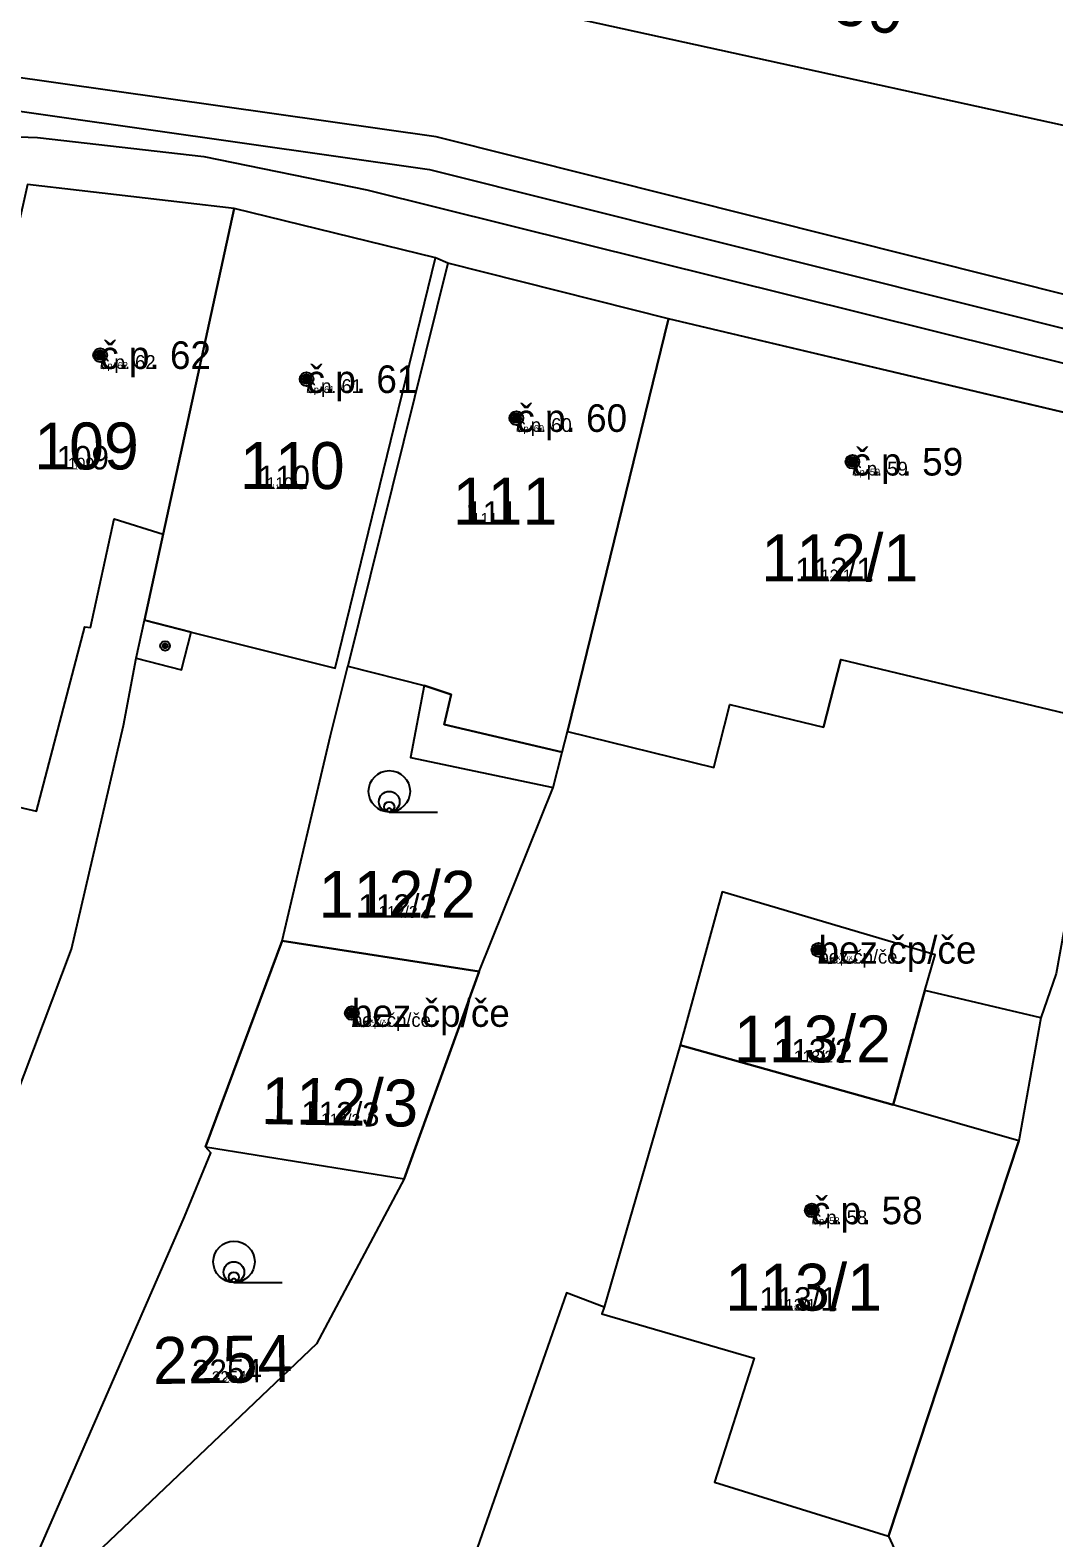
# Model space of a CAD drawing. Extents: x -744652 to -739090, y -980828 to -975855.
# Drawn here: x -742656.4 to -742619.3, y -978675.6 to -978620.9 of the extents above; entities that cross this region are included whole.
import ezdxf

# ---------------------------------------------------------------- set-up
doc = ezdxf.new("R2010")
doc.units = 0
for name, color, linetype in [('KAT_02_hranice parcel', 7, 'Continuous'), ('KAT_03_1000_st čísla parcelní', 7, 'Continuous'), ('KAT_03_1000_čísla parcelní', 7, 'Continuous'), ('KAT_03_1000_čísla popisná', 7, 'Continuous'), ('KAT_03_100_st čísla parcelní', 7, 'Continuous'), ('KAT_03_100_čísla parcelní', 7, 'Continuous'), ('KAT_03_100_čísla popisná', 7, 'Continuous'), ('KAT_03_250_st čísla parcelní', 7, 'Continuous'), ('KAT_03_250_čísla parcelní', 7, 'Continuous'), ('KAT_03_250_čísla popisná', 7, 'Continuous'), ('KAT_03_500_st čísla parcelní', 7, 'Continuous'), ('KAT_03_500_čísla parcelní', 7, 'Continuous'), ('KAT_03_500_čísla popisná', 7, 'Continuous'), ('KAT_04_vnitřní kresba', 7, 'Continuous'), ('KAT_05_1000_značky kultur', 7, 'Continuous'), ('KAT_05_100_značky kultur', 7, 'Continuous'), ('KAT_05_250_značky kultur', 7, 'Continuous'), ('KAT_05_500_značky kultur', 7, 'Continuous'), ('KAT_07_1000_značky budov', 7, 'Continuous'), ('KAT_07_100_značky budov', 7, 'Continuous'), ('KAT_07_500_značky budov', 7, 'Continuous'), ('KAT_10_věcná břemena', 7, 'Continuous'), ('KAT_14_plocha_budovy', 7, 'Continuous')]:
    doc.layers.add(name, color=color, linetype=linetype)

msp = doc.modelspace()

# ---------------------------------------------------------------- linework, layer by layer
at = {"layer": 'KAT_02_hranice parcel'}
for p, q in [((-742648.99, -978627.41), (-742656.48, -978626.54)), ((-742641.69, -978629.19), (-742648.99, -978627.41)), ((-742641.24, -978629.39), (-742644.87, -978643.99)), ((-742641.24, -978629.39), (-742641.69, -978629.19)), ((-742633.24, -978631.41), (-742641.24, -978629.39)), ((-742616.02, -978635.48), (-742633.24, -978631.41)), ((-742640.11, -978655.05), (-742637.43, -978648.38)), ((-742650.02, -978661.4), (-742647.25, -978653.94)), ((-742647.25, -978653.94), (-742640.11, -978655.05)), ((-742640.11, -978655.05), (-742642.83, -978662.56)), ((-742619.75, -978656.72), (-742623.95, -978655.73)), ((-742650.02, -978661.4), (-742642.83, -978662.56))]:
    msp.add_line(p, q, dxfattribs=at)
for points in [[(-742522.65, -978636.07), (-742549.97, -978633.28), (-742570.9, -978630.86), (-742578.86, -978629.74), (-742582.72, -978630.81), (-742604.63, -978627.47), (-742606.59, -978627.11), (-742643.73, -978618.95), (-742648.55, -978617.06), (-742656.38, -978615.82), (-742687.27, -978612.16), (-742690.29, -978611.84), (-742693.32, -978611.73), (-742696.29, -978611.66), (-742699.31, -978611.74), (-742704.32, -978612.08), (-742722.21, -978614.75), (-742725.22, -978615.06), (-742728.22, -978615.18), (-742731.2, -978615.09), (-742734.19, -978614.83)], [(-742703.15, -978625.25), (-742703.26, -978623.39), (-742676.2, -978624.12), (-742656.11, -978624.83), (-742650.09, -978625.52), (-742644.18, -978626.73), (-742615.87, -978633.77)], [(-742652.54, -978643.69), (-742652.24, -978642.32), (-742651.56, -978639.2), (-742648.99, -978627.41)], [(-742652.54, -978643.69), (-742650.89, -978644.12), (-742650.54, -978642.75), (-742645.32, -978644.06), (-742641.69, -978629.19)], [(-742637.43, -978648.38), (-742637.1, -978647.1), (-742636.9, -978646.35), (-742633.24, -978631.41)], [(-742616.02, -978635.48), (-742618.77, -978652.77), (-742619.2, -978655.12), (-742619.75, -978656.72)], [(-742658.67, -978664.27), (-742654.88, -978654.24), (-742653, -978646.13), (-742652.54, -978643.69)], [(-742647.25, -978653.94), (-742645.49, -978646.5), (-742644.87, -978643.99)], [(-742644.87, -978643.99), (-742642.1, -978644.68), (-742642.59, -978647.29), (-742637.43, -978648.38)], [(-742623.95, -978655.73), (-742623.58, -978654.44), (-742631.3, -978652.16), (-742632.82, -978657.71)], [(-742623.95, -978655.73), (-742625.1, -978659.88), (-742632.82, -978657.71)], [(-742619.75, -978656.72), (-742620.55, -978661.18), (-742625.27, -978675.5), (-742624.7, -978676.73), (-742624.09, -978685.66)], [(-742632.82, -978657.71), (-742635.58, -978667.21), (-742636.94, -978666.69), (-742642.55, -978682.7), (-742646.97, -978692.83)], [(-742656.28, -978676.53), (-742650.78, -978663.93), (-742649.83, -978661.61), (-742650.02, -978661.4)], [(-742642.83, -978662.56), (-742646, -978668.53), (-742655.01, -978677.1)]]:
    msp.add_lwpolyline(points, dxfattribs=at)
at = {"layer": 'KAT_03_1000_čísla popisná'}
for centre in [(-742653.84, -978632.72), (-742653.84, -978632.72), (-742646.36, -978633.59), (-742646.36, -978633.59), (-742638.76, -978635), (-742638.76, -978635), (-742626.58, -978636.58), (-742626.58, -978636.58), (-742627.81, -978654.26), (-742627.81, -978654.26), (-742644.72, -978656.55), (-742644.72, -978656.55), (-742628.05, -978663.7), (-742628.05, -978663.7)]:
    msp.add_circle(centre, 0.25, dxfattribs=at)
at = {"layer": 'KAT_03_100_čísla popisná'}
for centre in [(-742653.84, -978632.72), (-742653.84, -978632.72), (-742646.36, -978633.59), (-742646.36, -978633.59), (-742638.76, -978635), (-742638.76, -978635), (-742626.58, -978636.58), (-742626.58, -978636.58), (-742627.81, -978654.26), (-742627.81, -978654.26), (-742644.72, -978656.55), (-742644.72, -978656.55), (-742628.05, -978663.7), (-742628.05, -978663.7)]:
    msp.add_circle(centre, 0.025, dxfattribs=at)
at = {"layer": 'KAT_03_250_čísla popisná'}
for centre in [(-742653.84, -978632.72), (-742653.84, -978632.72), (-742646.36, -978633.59), (-742646.36, -978633.59), (-742638.76, -978635), (-742638.76, -978635), (-742626.58, -978636.58), (-742626.58, -978636.58), (-742627.81, -978654.26), (-742627.81, -978654.26), (-742644.72, -978656.55), (-742644.72, -978656.55), (-742628.05, -978663.7), (-742628.05, -978663.7)]:
    msp.add_circle(centre, 0.0625, dxfattribs=at)
at = {"layer": 'KAT_03_500_čísla popisná'}
for centre in [(-742653.84, -978632.72), (-742653.84, -978632.72), (-742646.36, -978633.59), (-742646.36, -978633.59), (-742638.76, -978635), (-742638.76, -978635), (-742626.58, -978636.58), (-742626.58, -978636.58), (-742627.81, -978654.26), (-742627.81, -978654.26), (-742644.72, -978656.55), (-742644.72, -978656.55), (-742628.05, -978663.7), (-742628.05, -978663.7)]:
    msp.add_circle(centre, 0.125, dxfattribs=at)
at = {"layer": 'KAT_04_vnitřní kresba'}
for p, q in [((-742654.19, -978642.59), (-742653.34, -978638.65)), ((-742653.34, -978638.65), (-742651.56, -978639.2)), ((-742656.15, -978649.24), (-742654.4, -978642.56)), ((-742654.4, -978642.56), (-742654.19, -978642.59)), ((-742650.54, -978642.75), (-742652.24, -978642.32)), ((-742627, -978643.74), (-742627.63, -978646.19)), ((-742627, -978643.74), (-742618.58, -978645.76)), ((-742641.12, -978645.01), (-742642.1, -978644.68)), ((-742641.38, -978646.1), (-742641.12, -978645.01)), ((-742631.6, -978647.66), (-742631.02, -978645.37)), ((-742631.02, -978645.37), (-742627.63, -978646.19)), ((-742637.1, -978647.1), (-742641.38, -978646.1)), ((-742636.9, -978646.35), (-742631.6, -978647.66)), ((-742661.63, -978647.97), (-742656.15, -978649.24)), ((-742620.55, -978661.18), (-742625.1, -978659.88)), ((-742635.58, -978667.21), (-742635.66, -978667.44)), ((-742635.66, -978667.44), (-742630.14, -978669.05)), ((-742630.14, -978669.05), (-742631.58, -978673.54)), ((-742631.58, -978673.54), (-742625.27, -978675.5))]:
    msp.add_line(p, q, dxfattribs=at)
at = {"layer": 'KAT_05_1000_značky kultur'}
for p, q in [((-742643.363, -978649.27), (-742641.613, -978649.27)), ((-742648.993, -978666.31), (-742647.243, -978666.31))]:
    msp.add_line(p, q, dxfattribs=at)
for centre in [(-742643.363, -978648.52), (-742648.993, -978665.56)]:
    msp.add_circle(centre, 0.75, dxfattribs=at)
at = {"layer": 'KAT_05_100_značky kultur'}
for p, q in [((-742643.369, -978649.27), (-742643.194, -978649.27)), ((-742648.999, -978666.31), (-742648.824, -978666.31))]:
    msp.add_line(p, q, dxfattribs=at)
for centre in [(-742643.369, -978649.195), (-742648.999, -978666.235)]:
    msp.add_circle(centre, 0.075, dxfattribs=at)
at = {"layer": 'KAT_05_250_značky kultur'}
for p, q in [((-742643.368, -978649.27), (-742642.931, -978649.27)), ((-742648.998, -978666.31), (-742648.561, -978666.31))]:
    msp.add_line(p, q, dxfattribs=at)
for centre in [(-742643.368, -978649.082), (-742648.998, -978666.122)]:
    msp.add_circle(centre, 0.187, dxfattribs=at)
at = {"layer": 'KAT_05_500_značky kultur'}
for p, q in [((-742643.367, -978649.27), (-742642.492, -978649.27)), ((-742648.997, -978666.31), (-742648.122, -978666.31))]:
    msp.add_line(p, q, dxfattribs=at)
for centre in [(-742643.366, -978648.895), (-742648.996, -978665.935)]:
    msp.add_circle(centre, 0.375, dxfattribs=at)
at = {"layer": 'KAT_07_1000_značky budov'}
for centre in [(-742653.847, -978632.719), (-742646.367, -978633.589), (-742638.767, -978634.999), (-742626.587, -978636.579), (-742651.487, -978643.249), (-742627.817, -978654.259), (-742644.727, -978656.549), (-742628.057, -978663.699)]:
    msp.add_circle(centre, 0.175, dxfattribs=at)
at = {"layer": 'KAT_07_100_značky budov'}
for centre in [(-742653.841, -978632.72), (-742646.361, -978633.59), (-742638.761, -978635), (-742626.581, -978636.58), (-742651.481, -978643.25), (-742627.811, -978654.26), (-742644.721, -978656.55), (-742628.051, -978663.7)]:
    msp.add_circle(centre, 0.0175, dxfattribs=at)
at = {"layer": 'KAT_07_500_značky budov'}
for centre, radius in [((-742653.843, -978632.72), 0.0875), ((-742653.842, -978632.72), 0.0438), ((-742646.363, -978633.59), 0.0875), ((-742646.362, -978633.59), 0.0438), ((-742638.763, -978635), 0.0875), ((-742638.762, -978635), 0.0438), ((-742626.583, -978636.58), 0.0875), ((-742626.582, -978636.58), 0.0438), ((-742651.483, -978643.25), 0.0875), ((-742651.482, -978643.25), 0.0438), ((-742627.813, -978654.26), 0.0875), ((-742627.812, -978654.26), 0.0438), ((-742644.723, -978656.55), 0.0875), ((-742644.722, -978656.55), 0.0438), ((-742628.053, -978663.7), 0.0875), ((-742628.052, -978663.7), 0.0438)]:
    msp.add_circle(centre, radius, dxfattribs=at)
at = {"layer": 'KAT_10_věcná břemena'}
msp.add_lwpolyline([(-742612.55, -978632.12), (-742641.67, -978624.81), (-742669.08, -978620.92), (-742706.88, -978620.85), (-742736.16, -978619.17), (-742737.02, -978621.05), (-742706.92, -978622.05), (-742669.16, -978622.12), (-742641.91, -978625.99), (-742612.75, -978633.3)], dxfattribs=at)
at = {"layer": 'KAT_14_plocha_budovy'}
for points in [[(-742660.03, -978642.4), (-742661.63, -978647.97), (-742656.15, -978649.24), (-742654.4, -978642.56), (-742654.19, -978642.59), (-742653.34, -978638.65), (-742651.56, -978639.2), (-742648.99, -978627.41), (-742656.48, -978626.54)], [(-742652.24, -978642.32), (-742650.54, -978642.75), (-742645.32, -978644.06), (-742641.69, -978629.19), (-742648.99, -978627.41), (-742651.56, -978639.2)], [(-742633.24, -978631.41), (-742641.24, -978629.39), (-742644.87, -978643.99), (-742642.1, -978644.68), (-742641.12, -978645.01), (-742641.38, -978646.1), (-742637.1, -978647.1), (-742636.9, -978646.35)], [(-742633.24, -978631.41), (-742636.9, -978646.35), (-742631.6, -978647.66), (-742631.02, -978645.37), (-742627.63, -978646.19), (-742627, -978643.74), (-742618.58, -978645.76), (-742616.02, -978635.48)], [(-742632.82, -978657.71), (-742625.1, -978659.88), (-742623.95, -978655.73), (-742623.58, -978654.44), (-742631.3, -978652.16)], [(-742647.25, -978653.94), (-742650.02, -978661.4), (-742642.83, -978662.56), (-742640.11, -978655.05)], [(-742635.58, -978667.21), (-742635.66, -978667.44), (-742630.14, -978669.05), (-742631.58, -978673.54), (-742625.27, -978675.5), (-742620.55, -978661.18), (-742625.1, -978659.88), (-742632.82, -978657.71)]]:
    msp.add_lwpolyline(points, close=True, dxfattribs=at)

# ---------------------------------------------------------------- texts
at = {"layer": 'KAT_03_1000_st čísla parcelní'}
for s, p in [('109', (-742656.234, -978636.86)), ('110', (-742648.774, -978637.57)), ('111', (-742641.064, -978638.86)), ('112/1', (-742629.883, -978640.91)), ('113/2', (-742630.873, -978658.34)), ('113/1', (-742631.193, -978667.33))]:
    msp.add_text(s, height=1.7, dxfattribs=at).set_placement(p)
msp.add_text('112/3', height=1.7, rotation=359, dxfattribs=at).set_placement((-742648.017, -978660.571))
at = {"layer": 'KAT_03_1000_čísla parcelní'}
for s, rotation, p in [('2054/50', 349, (-742632.949, -978619.582)), ('2254', 1, (-742651.921, -978669.993))]:
    msp.add_text(s, height=1.7, rotation=rotation, dxfattribs=at).set_placement(p)
msp.add_text('112/2', height=1.7, dxfattribs=at).set_placement((-742645.923, -978653.1))
at = {"layer": 'KAT_03_1000_čísla popisná'}
for s, height, p in [('č.p. 62', 1, (-742653.84, -978633.22)), ('č.p. 61', 1, (-742646.36, -978634.09)), ('č.p. 60', 1, (-742638.76, -978635.5)), ('č.p. 59', 1, (-742626.58, -978637.08)), ('109', 0.017, (-742654.617, -978636.86)), ('110', 0.017, (-742647.502, -978637.57)), ('111', 0.017, (-742640.163, -978638.86)), ('112/1', 0.017, (-742627.445, -978640.91)), ('bez čp/če', 1, (-742627.81, -978654.76)), ('bez čp/če', 1, (-742644.72, -978657.05)), ('113/2', 0.017, (-742628.004, -978658.34)), ('č.p. 58', 1, (-742628.05, -978664.2)), ('113/1', 0.017, (-742628.742, -978667.33))]:
    msp.add_text(s, height=height, dxfattribs=at).set_placement(p)
msp.add_text('112/3', height=0.017, rotation=359, dxfattribs=at).set_placement((-742645.149, -978660.621))
at = {"layer": 'KAT_03_100_st čísla parcelní'}
for s, p in [('109', (-742654.764, -978636.86)), ('110', (-742647.618, -978637.57)), ('111', (-742640.245, -978638.86)), ('112/1', (-742627.667, -978640.91)), ('113/2', (-742628.265, -978658.34)), ('113/1', (-742628.964, -978667.33))]:
    msp.add_text(s, height=0.17, dxfattribs=at).set_placement(p)
msp.add_text('112/3', height=0.17, rotation=359, dxfattribs=at).set_placement((-742645.409, -978660.617))
at = {"layer": 'KAT_03_100_čísla parcelní'}
msp.add_text('112/2', height=0.17, dxfattribs=at).set_placement((-742643.327, -978653.1))
msp.add_text('2254', height=0.17, rotation=1, dxfattribs=at).set_placement((-742649.368, -978669.948))
at = {"layer": 'KAT_03_100_čísla popisná'}
for s, height, p in [('č.p. 62', 0.1, (-742653.84, -978633.22)), ('č.p. 61', 0.1, (-742646.36, -978634.09)), ('č.p. 60', 0.1, (-742638.76, -978635.5)), ('109', 0.0017, (-742654.603, -978636.86)), ('č.p. 59', 0.1, (-742626.58, -978637.08)), ('110', 0.0017, (-742647.49, -978637.57)), ('111', 0.0017, (-742640.155, -978638.86)), ('112/1', 0.0017, (-742627.423, -978640.91)), ('bez čp/če', 0.1, (-742627.81, -978654.76)), ('bez čp/če', 0.1, (-742644.72, -978657.05)), ('113/2', 0.0017, (-742627.978, -978658.34)), ('č.p. 58', 0.1, (-742628.05, -978664.2)), ('113/1', 0.0017, (-742628.719, -978667.33))]:
    msp.add_text(s, height=height, dxfattribs=at).set_placement(p)
msp.add_text('112/3', height=0.0017, rotation=359, dxfattribs=at).set_placement((-742645.123, -978660.622))
at = {"layer": 'KAT_03_250_st čísla parcelní'}
for s, p in [('109', (-742655.009, -978636.86)), ('110', (-742647.81, -978637.57)), ('111', (-742640.381, -978638.86)), ('112/1', (-742628.036, -978640.91)), ('113/2', (-742628.7, -978658.34)), ('113/1', (-742629.336, -978667.33))]:
    msp.add_text(s, height=0.425, dxfattribs=at).set_placement(p)
msp.add_text('112/3', height=0.425, rotation=359, dxfattribs=at).set_placement((-742645.844, -978660.609))
at = {"layer": 'KAT_03_250_čísla parcelní'}
msp.add_text('112/2', height=0.425, dxfattribs=at).set_placement((-742643.76, -978653.1))
msp.add_text('2254', height=0.425, rotation=1, dxfattribs=at).set_placement((-742649.793, -978669.956))
at = {"layer": 'KAT_03_250_čísla popisná'}
for s, height, p in [('č.p. 62', 0.25, (-742653.84, -978633.22)), ('č.p. 61', 0.25, (-742646.36, -978634.09)), ('č.p. 60', 0.25, (-742638.76, -978635.5)), ('109', 0.00425, (-742654.605, -978636.86)), ('č.p. 59', 0.25, (-742626.58, -978637.08)), ('110', 0.00425, (-742647.492, -978637.57)), ('111', 0.00425, (-742640.156, -978638.86)), ('112/1', 0.00425, (-742627.426, -978640.91)), ('bez čp/če', 0.25, (-742627.81, -978654.76)), ('bez čp/če', 0.25, (-742644.72, -978657.05)), ('113/2', 0.00425, (-742627.982, -978658.34)), ('č.p. 58', 0.25, (-742628.05, -978664.2)), ('113/1', 0.00425, (-742628.723, -978667.33))]:
    msp.add_text(s, height=height, dxfattribs=at).set_placement(p)
msp.add_text('112/3', height=0.00425, rotation=359, dxfattribs=at).set_placement((-742645.127, -978660.621))
at = {"layer": 'KAT_03_500_st čísla parcelní'}
for s, p in [('109', (-742655.418, -978636.86)), ('110', (-742648.132, -978637.57)), ('111', (-742640.609, -978638.86)), ('112/1', (-742628.652, -978640.91)), ('113/2', (-742629.424, -978658.34)), ('113/1', (-742629.955, -978667.33))]:
    msp.add_text(s, height=0.85, dxfattribs=at).set_placement(p)
msp.add_text('112/3', height=0.85, rotation=359, dxfattribs=at).set_placement((-742646.568, -978660.596))
at = {"layer": 'KAT_03_500_čísla parcelní'}
msp.add_text('112/2', height=0.85, dxfattribs=at).set_placement((-742644.481, -978653.1))
msp.add_text('2254', height=0.85, rotation=1, dxfattribs=at).set_placement((-742650.502, -978669.968))
at = {"layer": 'KAT_03_500_čísla popisná'}
for s, height, p in [('č.p. 62', 0.5, (-742653.84, -978633.22)), ('č.p. 61', 0.5, (-742646.36, -978634.09)), ('č.p. 60', 0.5, (-742638.76, -978635.5)), ('č.p. 59', 0.5, (-742626.58, -978637.08)), ('109', 0.0085, (-742654.609, -978636.86)), ('110', 0.0085, (-742647.496, -978637.57)), ('111', 0.0085, (-742640.158, -978638.86)), ('112/1', 0.0085, (-742627.433, -978640.91)), ('bez čp/če', 0.5, (-742627.81, -978654.76)), ('bez čp/če', 0.5, (-742644.72, -978657.05)), ('113/2', 0.0085, (-742627.99, -978658.34)), ('č.p. 58', 0.5, (-742628.05, -978664.2)), ('113/1', 0.0085, (-742628.729, -978667.33))]:
    msp.add_text(s, height=height, dxfattribs=at).set_placement(p)
msp.add_text('112/3', height=0.0085, rotation=359, dxfattribs=at).set_placement((-742645.134, -978660.621))

doc.saveas('drawing.dxf')
